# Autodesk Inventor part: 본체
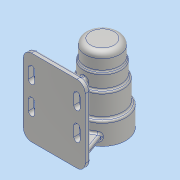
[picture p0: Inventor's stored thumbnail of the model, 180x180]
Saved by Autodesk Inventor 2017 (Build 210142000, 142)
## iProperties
Part Number: 본체
Material: 알루미늄 6061
Document SubType Name: Modeling
Designer: MRC
Density: 2.7 g/cm^3
Appearance: 알루미늄 - 평지
Author: MRC
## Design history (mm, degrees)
sketch "스케치1"
  geometry: L1 (0, -56)-(34, -56); L2 (34, -56)-(34, -24); L3 (34, -24)-(30, -24); L4 (30, -24)-(30, 10); L5 (30, 10)-(27, 10); L6 (27, 10)-(27, 32); L7 (27, 32)-(25, 32); L8 (25, 32)-(25, 56); L9 (25, 56)-(0, 56); L10 (0, -56)-(0, 56); L11 (21, -56)-(21, -41); L12 (21, -41)-(24, -41); L13 (24, -41)-(24, 13); L14 (24, 13)-(21, 13); L15 (21, 13)-(21, 25); L16 (21, 25)-(17.5, 25); L17 (17.5, 25)-(17.5, 43); L18 (17.5, 43)-(16, 43); L19 (16, 43)-(16, 47); L20 (16, 47)-(10.5, 47); L21 (10.5, 47)-(10.5, 50); L22 (10.5, 50)-(0, 50); L23 (-62, 56)-(-70, 56); L24 (-70, 56)-(-70, -56); L25 (-70, -56)-(-62, -56); L26 (-62, -56)-(-62, 56); 4 further points
  constraints: 52 end point, 13 perpendicular, 8 horizontal, 3 midpoint, 3 parallel, 2 horizontal alignment, 2 point on line, 2 vertical, 1 coincident, 1 vertical alignment
  dimensions: "d0" = 112 distance between parallel lines of L1 L9; "d5" = 24 distance from line of L6.end L9; "d6" = 46 distance between parallel lines of L5 L9; "d7" = 80 distance between parallel lines of L3 L9; "d8" = 68 diameter of L2 L10; "d9" = 60 diameter of L4 L10; "d10" = 54 diameter of L6 L10; "d11" = 50 diameter of L8 L10; "d12" = 42 diameter of L11 L10; "d13" = 15 distance of L11.start L11.end; "d14" = 48 diameter of L13 L10; "d15" = 54 distance of L12.end L13.end; "d16" = 12 distance of L14.end L15.end; "d17" = 18 distance of L16.end L17.end; "d18" = 35 diameter of L17 L10; "d19" = 32 diameter of L19 L10; "d20" = 21 diameter of L21 L10; "d21" = 4 distance between parallel lines of L18 L20; "d22" = 3 distance between parallel lines of L20 L22; "d23" = 70 distance between parallel lines of L24 L10; "d24" = 8 distance of L24.end L25.end
revolve "회전1" stored, may be unused: angle "d25" = 90 deg
extrude "돌출1" join sketch "스케치1" stored distance "d26" = 90; taper "d27" = 0 deg
sketch "스케치2"
  geometry: L1 (-25, 56)-(25, 56) reference; L2 (25, 56)-(25, 32) reference; L3 (25, 32)-(27, 32) reference; L4 (27, 32)-(27, 10) reference; L5 (27, 10)-(30, 10) reference; L6 (30, 10)-(30, -24) reference; L7 (30, -24)-(34, -24) reference; L8 (34, -24)-(34, -56) reference; L9 (34, -56)-(21, -56) reference; L10 (21, -56)-(21, -41) reference; L11 (21, -41)-(24, -41) reference; L12 (24, -41)-(24, 13) reference; L13 (24, 13)-(21, 13) reference; L14 (21, 13)-(21, 25) reference; L15 (21, 25)-(17.5, 25) reference; L16 (17.5, 25)-(17.5, 43) reference; L17 (17.5, 43)-(16, 43) reference; L18 (16, 43)-(16, 47) reference; L19 (16, 47)-(10.5, 47) reference; L20 (10.5, 47)-(10.5, 50) reference; L21 (10.5, 50)-(-10.5, 50) reference; L22 (-10.5, 50)-(-10.5, 47) reference; L23 (-10.5, 47)-(-16, 47) reference; L24 (-16, 47)-(-16, 43) reference; L25 (-16, 43)-(-17.5, 43) reference; L26 (-17.5, 43)-(-17.5, 25) reference; L27 (-17.5, 25)-(-21, 25) reference; L28 (-21, 25)-(-21, 13) reference; L29 (-21, 13)-(-24, 13) reference; L30 (-24, 13)-(-24, -41) reference; L31 (-24, -41)-(-21, -41) reference; L32 (-21, -41)-(-21, -56) reference; L33 (-21, -56)-(-34, -56) reference; L34 (-34, -56)-(-34, -24) reference; L35 (-34, -24)-(-30, -24) reference; L36 (-30, -24)-(-30, 10) reference; L37 (-30, 10)-(-27, 10) reference; L38 (-27, 10)-(-27, 32) reference; L39 (-27, 32)-(-25, 32) reference; L40 (-25, 32)-(-25, 56) reference; L41 (-62, 56)-(-62, -56) reference; L42 (-62, -56)-(-70, -56) reference; L43 (-70, -56)-(-70, 56) reference; L44 (-70, 56)-(-62, 56) reference; L45 (-62, 29)-(-26.114, 19.384); 1 further point
  constraints: 2 end point, 1 point on line
  dimensions: "d28" = 105 deg angle of L45 L41; "d29" = 85 distance from line of L42 L45.start
  node "절단 모서리 투영1"
node "작업 평면1"
sketch "스케치3"
  geometry: L1 (45, -62)-(45, -70) reference; L2 (45, -70)-(-45, -70) reference; L3 (-45, -70)-(-45, -62) reference; L4 (-45, -62)-(45, -62) reference; L5 (-45, -62)-(45, -62) reference; L6 (-37, -62)-(-23.409, -24.658); C1 r 21 at (0, 0) reference; 3 further points
  constraints: 2 end point, 1 point on line, 4 other
  dimensions: "d31" = 8 distance from line of L6.start L3; "d32" = 110 deg angle of L6 L4
feature "리브1" sketch "스케치3" dims "d33" = 40, "d34" = 8, "d35" = 0, "d36" = 0, "d37" = 1, "d38" = 1
feature "리브2" dims "d39" = 40, "d40" = 8, "d41" = 0, "d42" = 0, "d43" = 1, "d44" = 1
sketch "스케치4"
  geometry: L1 (0, 112)-(90, 112) reference; L2 (12, 92)-(12, 77); L3 (7.5, 92)-(7.5, 77); L4 (16.5, 77)-(16.5, 92); L5 (0, 0)-(0, 112) reference; L6 (0, 112)-(90, 112) reference; L7 (90, 112)-(90, 0) reference; L8 (90, 0)-(0, 0) reference; L9 (12, 52)-(12, 37); L10 (7.5, 52)-(7.5, 37); L11 (16.5, 37)-(16.5, 52); L12 (78, 92)-(78, 77); L13 (73.5, 92)-(73.5, 77); L14 (82.5, 77)-(82.5, 92); L15 (78, 52)-(78, 37); L16 (73.5, 52)-(73.5, 37); L17 (82.5, 37)-(82.5, 52); A1 r 4.5 centre (12, 92) between (16.5, 92) and (7.5, 92); A2 r 4.5 centre (12, 77) between (7.5, 77) and (16.5, 77); A3 r 4.5 centre (12, 52) between (16.5, 52) and (7.5, 52); A4 r 4.5 centre (12, 37) between (7.5, 37) and (16.5, 37); A5 r 4.5 centre (78, 92) between (82.5, 92) and (73.5, 92); A6 r 4.5 centre (78, 77) between (73.5, 77) and (82.5, 77); A7 r 4.5 centre (78, 52) between (82.5, 52) and (73.5, 52); A8 r 4.5 centre (78, 37) between (73.5, 37) and (82.5, 37); 5 further points
  constraints: 32 end point, 16 point on circle, 16 tangent, 8 centre point, 5 parallel, 4 midpoint, 3 equal length, 3 equal radius, 3 vertical, 2 vertical alignment, 1 horizontal alignment
  dimensions: "d45" = 15 distance of L2.start L2.end; "d46" = 9 distance between parallel lines of L3 L4; "d47" = 20 distance from line of L2.start L1; "d48" = 33 horizontal distance of point (45, 56) point (12, 84.5); "d49" = 25 distance of L9.start L2.end; "d50" = 33 horizontal distance of point (45, 56) L12.start; "d51" = 20 distance from line of L12.start L1
extrude "돌출2" cut sketch "스케치4" distance "d52" = 20; taper "d53" = 0 deg
fillet "모깎기1" dims "d54" = 12
fillet "모깎기2" dims "d55" = 0.3
sketch "스케치5"
  geometry: L1 (0, 0)-(22.84, 39.56); L2 (0, 0)-(-47.681, 0); C1 r 21 at (0, 0) reference; C2 r 34 at (0, 0) reference; 1 further point
  constraints: 4 end point, 1 horizontal, 1 point on line
  dimensions: "d56" = 120 deg angle of L2 L1; "d57" = 26 distance of C1.centre point (13, 22.517)
hole "구멍1" sketch "스케치5" at (13, 22.517) diameter "d58" = 3.242; stored, may be unused: countersink angle "d62" = 90 deg, drill point angle "d64" = 118 deg; dims "d59" = 8, "d60" = 4, "d61" = 2, "d63" = 11
chamfer "모따기2" distance "d73" = 1; stored, may be unused: second distance "d74" = 2, angle "d75" = 45 deg
fillet "모깎기5" dims "d76" = 3
fillet "모깎기6" dims "d77" = 3
fillet "모깎기7" dims "d78" = 3
sketch "스케치6"
  geometry: L1 (0, -109)-(66, -109) reference; 3 further points
  constraints: 1 midpoint, 1 vertical alignment, 1 other
  dimensions: "d79" = 12 distance from line of point (33, -97) L1
feature "엠보싱1" sketch "스케치6" dims "d0" = 112, "d5" = 24, "d6" = 46, "d7" = 80, "d8" = 68, "d9" = 60, "d10" = 54, "d11" = 50, "d12" = 42, "d13" = 15, "d14" = 48, "d15" = 54, "d16" = 12, "d17" = 18, "d18" = 35, "d19" = 32, "d20" = 21, "d21" = 4, "d22" = 3, "d23" = 70, "d24" = 8, "d80" = 0.5, "d81" = 0
fillet "모깎기8" dims "d82" = 8
node "솔리드1"
mirror "미러1"
pattern_circular "원형 패턴1" dims angle "d66" = 360 deg
node "절단 모서리 투영2"
node "절단 모서리 투영3"
other parameters: "d30" = -8
